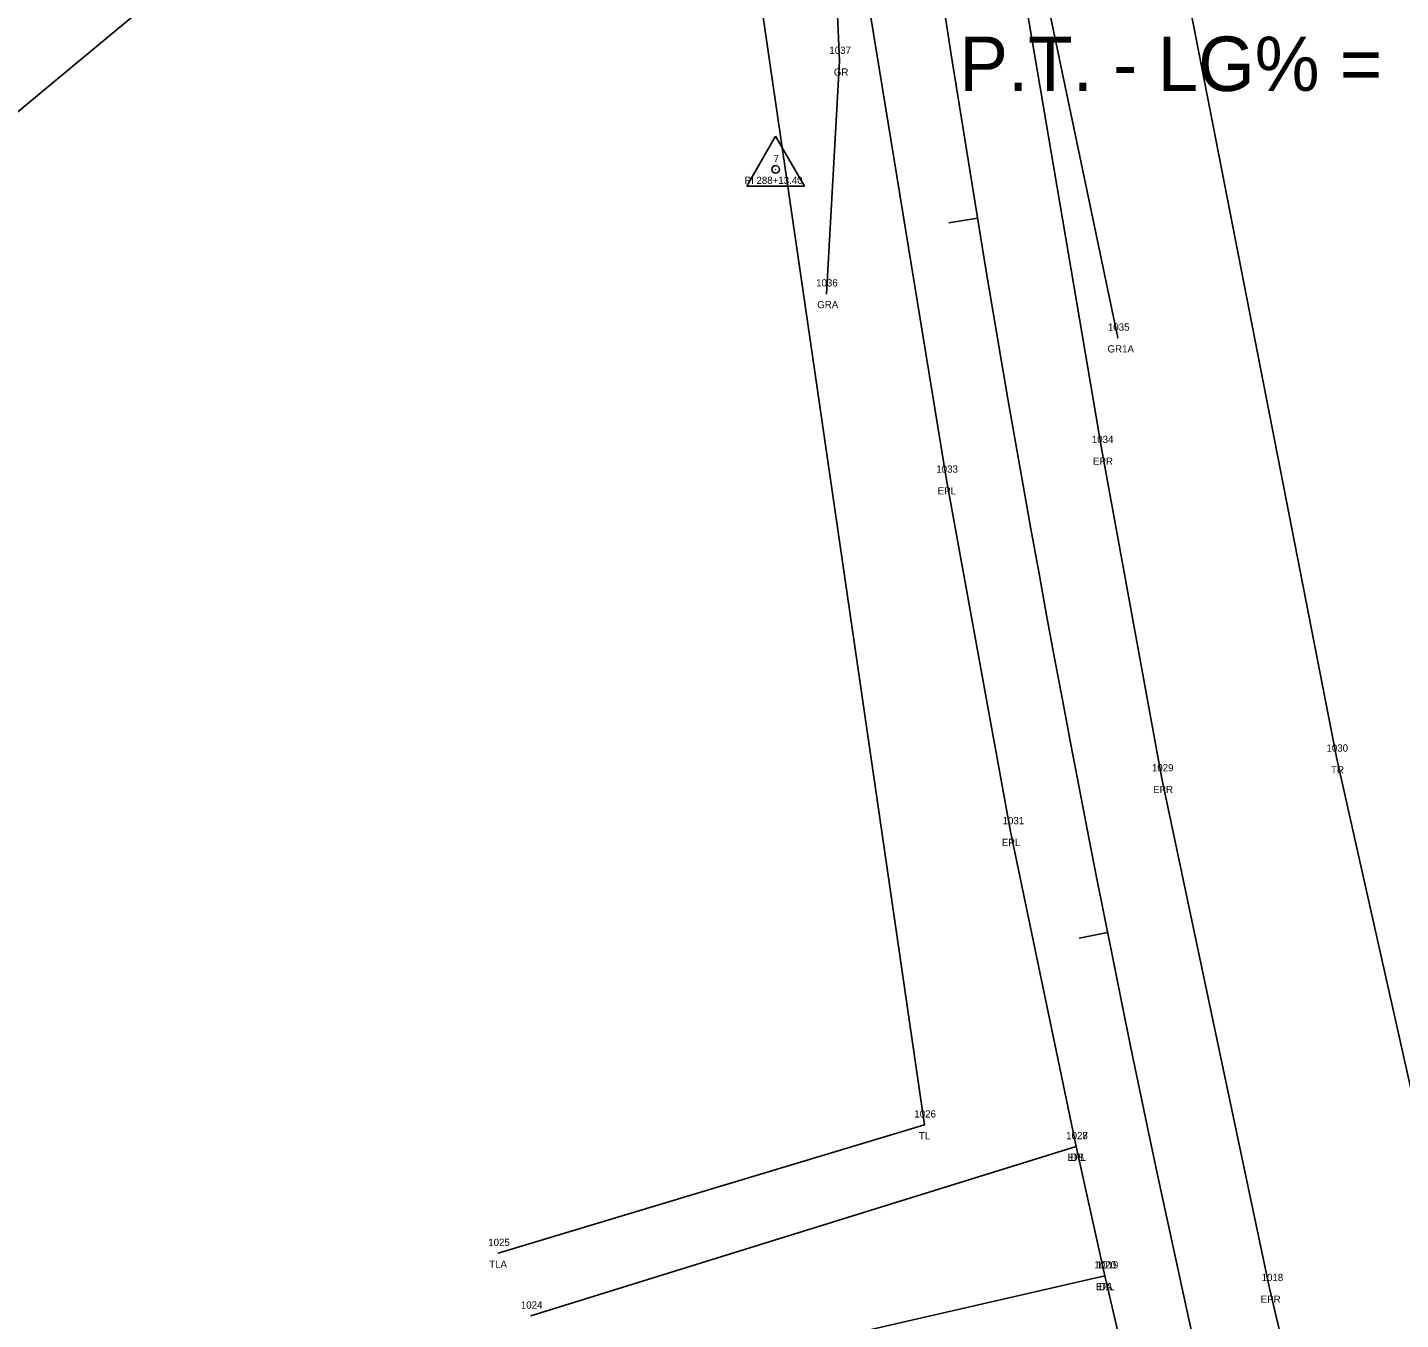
# Model space of a CAD drawing. Extents: x 2445178 to 2446205, y 790762 to 792372.
# Drawn here: x 2445595.7 to 2445784.7, y 791553.8 to 791731.8 of the extents above; entities that cross this region are included whole.
import ezdxf

# ---------------------------------------------------------------- set-up
doc = ezdxf.new("R2010")
doc.units = 0
for name, color, linetype in [('RD_EX_Driveway', 7, 'Continuous'), ('RD_EX_Driveway_txCode', 7, 'Continuous'), ('RD_EX_GuardRail', 7, 'Continuous'), ('RD_EX_GuardRail_txCode', 7, 'Continuous'), ('RD_EX_H2O', 7, 'Continuous'), ('RD_EX_Road', 7, 'Continuous'), ('RD_EX_Road_txCode', 7, 'Continuous'), ('RD_EX_VEG', 7, 'Continuous'), ('RD_EX_VEG_txCode', 7, 'Continuous'), ('RD_HC_Cl', 7, 'Continuous'), ('RD_HC_Data', 7, 'Continuous'), ('RD_HC_Data_Tic', 7, 'Continuous'), ('RD_HC_txCode', 7, 'Continuous'), ('RD_SMD_Locator', 7, 'Continuous')]:
    doc.layers.add(name, color=color, linetype=linetype)

msp = doc.modelspace()

# ---------------------------------------------------------------- linework, layer by layer
at = {"layer": 'RD_EX_Driveway'}
for p, q in [((2445664.99, 791554.3), (2445740.09, 791577.64)), ((2445744.01, 791559.83), (2445667.9, 791542.37))]:
    msp.add_line(p, q, dxfattribs=at)
at = {"layer": 'RD_EX_GuardRail'}
for points in [[(2445705.68, 791695.08), (2445707.49, 791727.11), (2445705.87, 791764.26), (2445697.05, 791819.94), (2445683.29, 791894.5)], [(2445745.83, 791688.99), (2445730.65, 791761.38), (2445730.26, 791764.17), (2445721.94, 791816.16), (2445720.14, 791835.32), (2445720.85, 791857.68), (2445725.34, 791893.43)]]:
    msp.add_lwpolyline(points, dxfattribs=at)
at = {"layer": 'RD_EX_H2O'}
msp.add_lwpolyline([(2445748.32, 791780.49), (2445701.12, 791774.43), (2445677.09, 791767.59), (2445662.39, 791761.56), (2445644.36, 791766.93), (2445623.55, 791762.71), (2445618.49, 791746.46), (2445607.67, 791748.78), (2445606.64, 791748.27), (2445612.18, 791734.98), (2445561.56, 791692.97), (2445554.1, 791670.89), (2445517.8, 791656.91), (2445473.7, 791621.85), (2445363.77, 791592.3), (2445292.26, 791558.82)], dxfattribs=at)
at = {"layer": 'RD_EX_Road'}
for points in [[(2445780.98, 791497.5), (2445766.72, 791558.1), (2445751.9, 791628.3), (2445743.63, 791673.52), (2445732.07, 791741.61), (2445728.16, 791765.65), (2445723.56, 791768), (2445722.11, 791770.23), (2445723.91, 791773.52), (2445727.13, 791775.28), (2445723.51, 791799.48), (2445721.07, 791816.02), (2445719.51, 791817.06), (2445719.65, 791821.33), (2445720.29, 791823.76), (2445714.87, 791872.94), (2445710.18, 791923.37), (2445705.3, 791989.12), (2445702.81, 792033.07), (2445700.66, 792091.77), (2445697.78, 792201.78), (2445695.41, 792302.8)], [(2445850.42, 791174.36), (2445823.13, 791264.7), (2445806.34, 791321.46), (2445789.41, 791379.89), (2445773.46, 791437.57), (2445759.36, 791494.22), (2445744.01, 791559.83), (2445740.09, 791577.64), (2445731.05, 791621.01), (2445722.21, 791669.43), (2445711, 791738.26), (2445706.49, 791765.2), (2445707.32, 791765.82), (2445706.36, 791771.19), (2445705.53, 791771.38), (2445701.96, 791795.92), (2445699.57, 791813.34), (2445693.24, 791870.48), (2445688.14, 791921.92), (2445683.42, 791987.19), (2445680.88, 792033.67), (2445678.74, 792090.55), (2445675.91, 792199.23), (2445673.61, 792301.11)]]:
    msp.add_lwpolyline(points, dxfattribs=at)
at = {"layer": 'RD_EX_VEG'}
for points in [[(2445895.98, 791185.85), (2445831.19, 791390.71), (2445805.05, 791501.58), (2445775.97, 791631.01), (2445748.83, 791769.92)], [(2445660.51, 791562.93), (2445719.21, 791580.62), (2445693.16, 791759.37)]]:
    msp.add_lwpolyline(points, dxfattribs=at)
at = {"layer": 'RD_HC_Cl'}
msp.add_arc((2448553.48, 792169.37), 2864.79, 181.3527, 196.84356, dxfattribs=at)
at = {"layer": 'RD_HC_Data'}
for p, q in [((2445694.72, 791709.91), (2445698.69, 791716.79)), ((2445698.69, 791716.79), (2445702.66, 791709.91)), ((2445694.72, 791709.91), (2445702.66, 791709.91))]:
    msp.add_line(p, q, dxfattribs=at)
msp.add_circle((2445698.69, 791712.2), 0.529, dxfattribs=at)
at = {"layer": 'RD_HC_Data_Tic'}
for p, q in [((2445726.5, 791705.49), (2445722.55, 791704.84)), ((2445744.41, 791607.11), (2445740.49, 791606.32))]:
    msp.add_line(p, q, dxfattribs=at)
at = {"layer": 'RD_SMD_Locator'}
for centre in [(2445707.49, 791727.11), (2445698.69, 791712.2), (2445705.68, 791695.08), (2445745.83, 791688.99), (2445743.63, 791673.52), (2445722.21, 791669.43), (2445775.97, 791631.01), (2445751.9, 791628.3), (2445731.05, 791621.01), (2445719.21, 791580.62), (2445740.09, 791577.64), (2445740.09, 791577.64), (2445660.51, 791562.93), (2445744.01, 791559.83), (2445744.01, 791559.83), (2445766.72, 791558.1), (2445664.99, 791554.3)]:
    msp.add_circle(centre, 0.001, dxfattribs=at)

# ---------------------------------------------------------------- texts
at = {"layer": 'RD_EX_Driveway_txCode'}
for s, p in [('1028', (2445738.71, 791578.64)), ('DB', (2445739.32, 791575.64)), ('1020', (2445742.59, 791560.83)), ('DA', (2445743.22, 791557.83)), ('1024', (2445663.61, 791555.3))]:
    msp.add_text(s, height=1, dxfattribs=at).set_placement(p)
at = {"layer": 'RD_EX_GuardRail_txCode'}
for s, p in [('1037', (2445706.1, 791728.11)), ('GR', (2445706.71, 791725.11)), ('1036', (2445704.27, 791696.08)), ('GRA', (2445704.42, 791693.08)), ('1035', (2445744.45, 791689.99)), ('GR1A', (2445744.4, 791686.99))]:
    msp.add_text(s, height=1, dxfattribs=at).set_placement(p)
at = {"layer": 'RD_EX_Road_txCode'}
for s, p in [('1034', (2445742.24, 791674.52)), ('1033', (2445720.83, 791670.43)), ('EPR', (2445742.4, 791671.52)), ('EPL', (2445721.01, 791667.43)), ('1029', (2445750.51, 791629.3)), ('EPR', (2445750.67, 791626.3)), ('1031', (2445729.95, 791622.01)), ('EPL', (2445729.85, 791619.01)), ('1027', (2445738.71, 791578.64)), ('EPL', (2445738.89, 791575.64)), ('1019', (2445742.91, 791560.83)), ('1018', (2445765.62, 791559.1)), ('EPL', (2445742.81, 791557.83)), ('EPR', (2445765.49, 791556.1))]:
    msp.add_text(s, height=1, dxfattribs=at).set_placement(p)
at = {"layer": 'RD_EX_VEG_txCode'}
for s, p in [('1030', (2445774.55, 791632.01)), ('TR', (2445775.18, 791629.01)), ('1026', (2445717.8, 791581.62)), ('TL', (2445718.43, 791578.62)), ('1025', (2445659.12, 791563.93)), ('TLA', (2445659.25, 791560.93))]:
    msp.add_text(s, height=1, dxfattribs=at).set_placement(p)
at = {"layer": 'RD_HC_Data'}
msp.add_text('P.T. - LG% = ', height=7.5, dxfattribs=at).set_placement((2445724, 791723))
at = {"layer": 'RD_HC_txCode'}
for s, p in [('7', (2445698.41, 791713.2)), ('PI 288+13.40', (2445694.42, 791710.2))]:
    msp.add_text(s, height=1, dxfattribs=at).set_placement(p)

doc.saveas('drawing.dxf')
